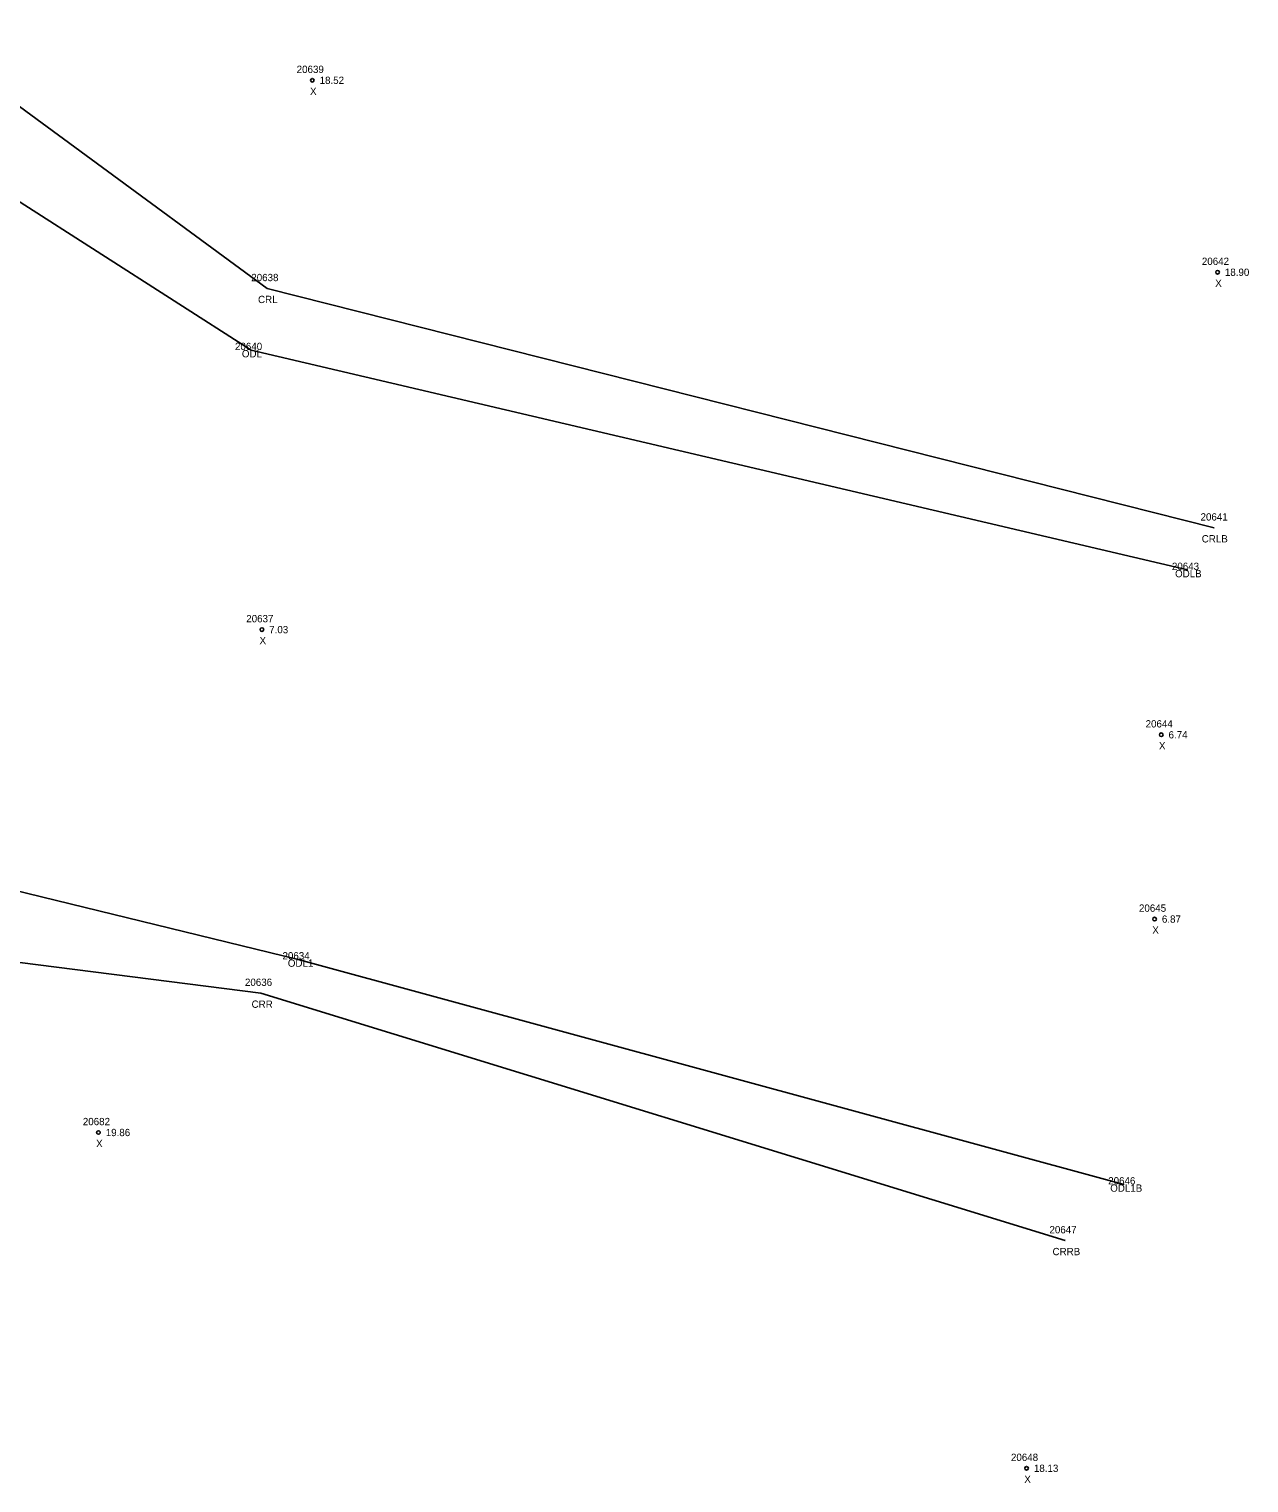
# Model space of a CAD drawing. Extents: x 2432729 to 2433340, y 684958 to 688103.
# Drawn here: x 2433172.9 to 2433339.9, y 685862.9 to 686061.9 of the extents above; entities that cross this region are included whole.
import ezdxf

# ---------------------------------------------------------------- set-up
doc = ezdxf.new("R2010")
doc.units = 0
for name, color, linetype in [('RD_EX_H2O', 7, 'Continuous'), ('RD_EX_H2O_txCode', 7, 'Continuous'), ('RD_Sketch8', 7, 'Continuous'), ('RD_SMD_Locator', 7, 'Continuous')]:
    doc.layers.add(name, color=color, linetype=linetype)

msp = doc.modelspace()

# ---------------------------------------------------------------- linework, layer by layer
at = {"layer": 'RD_EX_H2O'}
for points in [[(2432998.81, 686208.98), (2432991.26, 686158.53), (2433015.01, 686119.83), (2433043.41, 686089.59), (2433120.85, 686053.69), (2433150.58, 686051.7), (2433203.32, 686017.95), (2433331.51, 685987.84)], [(2433007.74, 686209.38), (2433001.59, 686166.41), (2433024.46, 686126.62), (2433051.58, 686097.06), (2433120.95, 686072.12), (2433152.82, 686065.09), (2433205.51, 686026.38), (2433335.15, 685993.61)], [(2432923.79, 686090.04), (2433021.62, 686006.73), (2433104.45, 685963.02), (2433133.66, 685953.1), (2433209.77, 685934.52), (2433322.81, 685903.72)], [(2432923.04, 686077.65), (2433019.93, 685999.69), (2433090.75, 685956.18), (2433102.59, 685949.56), (2433131.31, 685944.06), (2433132.23, 685945.04), (2433164.1, 685935.07), (2433204.66, 685929.9), (2433314.75, 685896.03)]]:
    msp.add_lwpolyline(points, dxfattribs=at)
at = {"layer": 'RD_SMD_Locator'}
for centre, radius in [((2433211.71, 686054.88), 0.25), ((2433335.62, 686028.6), 0.25), ((2433205.51, 686026.38), 0.001), ((2433203.32, 686017.95), 0.001), ((2433335.15, 685993.61), 0.001), ((2433331.51, 685987.84), 0.001), ((2433204.81, 685979.68), 0.25), ((2433327.91, 685965.28), 0.25), ((2433327, 685940.05), 0.25), ((2433209.77, 685934.52), 0.001), ((2433204.66, 685929.9), 0.001), ((2433182.44, 685910.83), 0.25), ((2433322.81, 685903.72), 0.001), ((2433314.75, 685896.03), 0.001), ((2433309.48, 685864.86), 0.25)]:
    msp.add_circle(centre, radius, dxfattribs=at)

# ---------------------------------------------------------------- texts
at = {"layer": 'RD_EX_H2O_txCode'}
for s, p in [('20638', (2433203.36, 686027.38)), ('CRL', (2433204.28, 686024.38)), ('20640', (2433201.13, 686017.95)), ('ODL', (2433202.07, 686016.95)), ('20641', (2433333.29, 685994.61)), ('CRLB', (2433333.45, 685991.61)), ('20643', (2433329.37, 685987.84)), ('ODLB', (2433329.8, 685986.84)), ('20634', (2433207.63, 685934.52)), ('ODL1', (2433208.36, 685933.52)), ('20636', (2433202.49, 685930.9)), ('CRR', (2433203.4, 685927.9)), ('20646', (2433320.65, 685903.72)), ('ODL1B', (2433320.93, 685902.72)), ('20647', (2433312.61, 685897.03)), ('CRRB', (2433313.03, 685894.03))]:
    msp.add_text(s, height=1, dxfattribs=at).set_placement(p)
at = {"layer": 'RD_Sketch8'}
for s, p in [('20639', (2433209.57, 686055.88)), ('18.52', (2433212.71, 686054.38)), ('X', (2433211.4, 686052.88)), ('20642', (2433333.47, 686029.6)), ('18.90', (2433336.62, 686028.1)), ('X', (2433335.3, 686026.6)), ('20637', (2433202.67, 685980.68)), ('X', (2433204.49, 685977.68)), ('7.03', (2433205.81, 685979.18)), ('20644', (2433325.77, 685966.28)), ('6.74', (2433328.91, 685964.78)), ('X', (2433327.6, 685963.28)), ('20645', (2433324.86, 685941.05)), ('X', (2433326.69, 685938.05)), ('6.87', (2433328, 685939.55)), ('20682', (2433180.3, 685911.83)), ('19.86', (2433183.44, 685910.33)), ('X', (2433182.12, 685908.83)), ('20648', (2433307.34, 685865.86)), ('18.13', (2433310.48, 685864.36)), ('X', (2433309.17, 685862.86))]:
    msp.add_text(s, height=1, dxfattribs=at).set_placement(p)

doc.saveas('drawing.dxf')
